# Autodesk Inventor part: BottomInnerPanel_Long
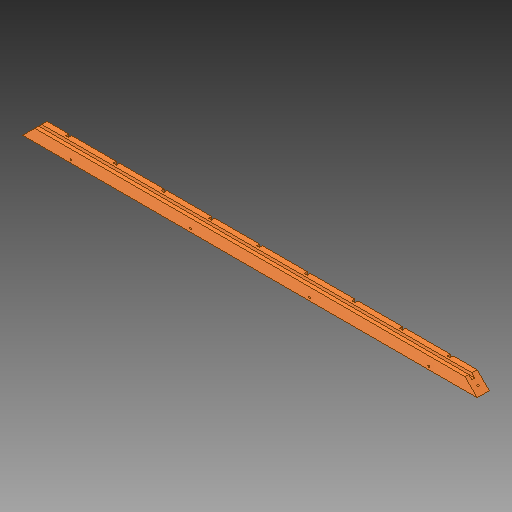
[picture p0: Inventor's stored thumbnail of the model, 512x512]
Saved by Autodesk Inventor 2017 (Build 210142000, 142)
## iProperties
Created: 2017-05
Part Number: BottomInnerPanel_Long
Material: Generic
Document SubType Name: Modeling
Designer: Savy
Density: 1 g/cm^3
Appearance: Default
Author: Savy
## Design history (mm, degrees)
feature "SOLID1"
body "Solid1"
